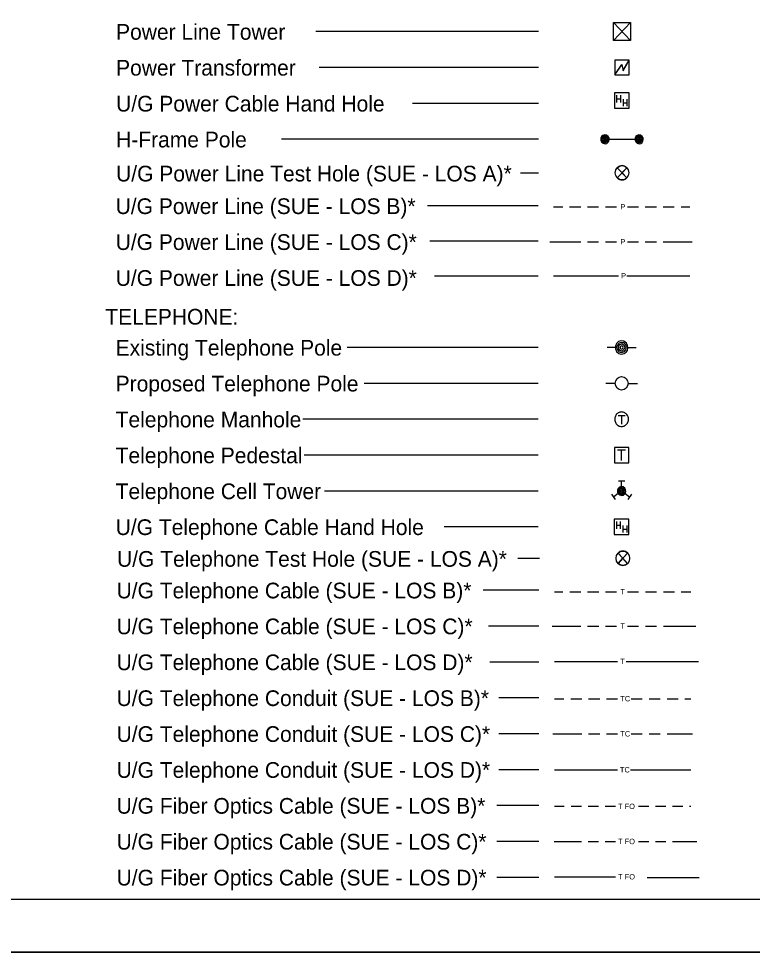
# Model space of a CAD drawing. Extents: x 2025847 to 2026166, y 840763 to 840870.
# Drawn here: x 2026094.71 to 2026130.13, y 840778.42 to 840823.5 of the extents above; entities that cross this region are included whole.
import ezdxf

# ---------------------------------------------------------------- set-up
doc = ezdxf.new("R2010")
doc.units = 0
for name, color, linetype in [('Exist Utilities Power Test Hole SUE LOS A CELL', 7, 'Continuous'), ('Exist Utilities Telephone Test Hole SUE LOS A CELL', 7, 'Continuous'), ('Sheet_Plan', 7, 'Continuous'), ('Sheet_Plot_Border_Outside_CELL', 7, 'Continuous'), ('Sheet_Symbology', 7, 'Continuous'), ('z - Construction', 7, 'Continuous')]:
    doc.layers.add(name, color=color, linetype=linetype)

msp = doc.modelspace()

# ---------------------------------------------------------------- linework, layer by layer
at = {"layer": 'Exist Utilities Power Test Hole SUE LOS A CELL'}
for points in [[(2026124.072, 840816.309), (2026123.607, 840815.819), (2026123.84, 840816.064), (2026123.607, 840816.309), (2026124.072, 840815.819)], [(2026123.607, 840816.309), (2026123.84, 840816.064), (2026124.072, 840816.309)], [(2026124.072, 840815.819), (2026123.84, 840816.064), (2026123.607, 840815.819)]]:
    msp.add_lwpolyline(points, dxfattribs=at)
for start_param, end_param in [(2.356194, 3.926991), (5.497787, 7.068583)]:
    msp.add_ellipse((2026123.84, 840816.064), major_axis=(0, -0.346), ratio=0.95, start_param=start_param, end_param=end_param, dxfattribs=at)
msp.add_ellipse((2026123.84, 840816.064), major_axis=(0, -0.346), ratio=0.95, dxfattribs=at)
at = {"layer": 'Exist Utilities Telephone Test Hole SUE LOS A CELL'}
for points in [[(2026124.111, 840797.692), (2026123.646, 840797.203), (2026123.879, 840797.448), (2026123.646, 840797.692), (2026124.111, 840797.203)], [(2026123.646, 840797.692), (2026123.879, 840797.448), (2026124.111, 840797.692)], [(2026124.111, 840797.203), (2026123.879, 840797.448), (2026123.646, 840797.203)]]:
    msp.add_lwpolyline(points, dxfattribs=at)
msp.add_ellipse((2026123.879, 840797.448), major_axis=(0, -0.346), ratio=0.95, dxfattribs=at)
for start_param, end_param in [(2.356194, 3.926991), (5.497787, 7.068583)]:
    msp.add_ellipse((2026123.879, 840797.448), major_axis=(0, -0.346), ratio=0.95, start_param=start_param, end_param=end_param, dxfattribs=at)
at = {"layer": 'Sheet_Plan'}
msp.add_line((2026024.668, 840780.981), (2026164.546, 840780.981), dxfattribs=at)
at = {"layer": 'Sheet_Plot_Border_Outside_CELL'}
msp.add_lwpolyline([(2026023.879, 840870.085), (2026165.546, 840870.085), (2026165.546, 840778.419), (2026023.879, 840778.419)], close=True, dxfattribs=at)
at = {"layer": 'Sheet_Symbology'}
for p, q in [((2026124.255, 840823.316), (2026123.433, 840822.45)), ((2026124.255, 840822.45), (2026123.433, 840823.316)), ((2026119.807, 840822.881), (2026109.051, 840822.881)), ((2026119.807, 840821.148), (2026109.218, 840821.148)), ((2026123.572, 840819.812), (2026123.572, 840819.463)), ((2026123.572, 840819.635), (2026123.762, 840819.635)), ((2026123.762, 840819.812), (2026123.762, 840819.463)), ((2026123.889, 840819.622), (2026123.889, 840819.273)), ((2026124.079, 840819.622), (2026124.079, 840819.273)), ((2026119.807, 840819.415), (2026113.725, 840819.415)), ((2026123.889, 840819.444), (2026124.079, 840819.444)), ((2026119.807, 840817.682), (2026107.403, 840817.682)), ((2026123.019, 840817.682), (2026124.665, 840817.682)), ((2026119.807, 840816.037), (2026118.932, 840816.037)), ((2026119.785, 840814.463), (2026114.441, 840814.463)), ((2026120.527, 840814.421), (2026120.979, 840814.421)), ((2026121.309, 840814.421), (2026121.844, 840814.421)), ((2026122.173, 840814.421), (2026122.708, 840814.421)), ((2026123.037, 840814.421), (2026123.572, 840814.421)), ((2026124.099, 840814.421), (2026124.634, 840814.421)), ((2026124.963, 840814.421), (2026125.498, 840814.421)), ((2026125.828, 840814.421), (2026126.363, 840814.421)), ((2026126.692, 840814.421), (2026127.112, 840814.421)), ((2026119.785, 840812.763), (2026114.567, 840812.763)), ((2026120.36, 840812.73), (2026121.844, 840812.73)), ((2026122.173, 840812.73), (2026122.708, 840812.73)), ((2026123.037, 840812.73), (2026123.572, 840812.73)), ((2026124.099, 840812.73), (2026124.634, 840812.73)), ((2026124.963, 840812.73), (2026125.498, 840812.73)), ((2026125.828, 840812.73), (2026127.229, 840812.73)), ((2026119.785, 840811.064), (2026114.789, 840811.064)), ((2026120.527, 840811.088), (2026123.662, 840811.088)), ((2026124.073, 840811.088), (2026127.112, 840811.088)), ((2026119.785, 840807.628), (2026110.574, 840807.628)), ((2026123.515, 840807.628), (2026123.12, 840807.628)), ((2026124.123, 840807.628), (2026124.518, 840807.628)), ((2026119.785, 840805.895), (2026111.383, 840805.895)), ((2026123.514, 840805.894), (2026123.051, 840805.894)), ((2026124.131, 840805.894), (2026124.594, 840805.894)), ((2026123.99, 840804.325), (2026123.651, 840804.325)), ((2026123.819, 840804.325), (2026123.819, 840803.931)), ((2026119.785, 840804.162), (2026108.436, 840804.162)), ((2026123.627, 840802.69), (2026124.012, 840802.69)), ((2026123.819, 840802.168), (2026123.819, 840802.69)), ((2026119.785, 840802.429), (2026108.494, 840802.429)), ((2026123.665, 840801.186), (2026123.974, 840801.186)), ((2026123.819, 840800.909), (2026123.819, 840801.186)), ((2026119.785, 840800.696), (2026109.477, 840800.696)), ((2026123.527, 840800.282), (2026123.35, 840800.548)), ((2026123.654, 840800.574), (2026123.438, 840800.415)), ((2026123.985, 840800.574), (2026124.201, 840800.415)), ((2026124.29, 840800.548), (2026124.112, 840800.282)), ((2026119.785, 840798.963), (2026115.254, 840798.963)), ((2026123.567, 840799.225), (2026123.567, 840798.876)), ((2026123.567, 840799.047), (2026123.756, 840799.047)), ((2026123.756, 840799.225), (2026123.756, 840798.876)), ((2026123.884, 840799.035), (2026123.884, 840798.686)), ((2026123.884, 840798.857), (2026124.073, 840798.857)), ((2026124.073, 840799.035), (2026124.073, 840798.686)), ((2026119.852, 840797.431), (2026118.81, 840797.431)), ((2026119.83, 840795.904), (2026117.131, 840795.904)), ((2026120.572, 840795.835), (2026120.985, 840795.835)), ((2026121.314, 840795.835), (2026121.849, 840795.835)), ((2026122.179, 840795.835), (2026122.714, 840795.835)), ((2026123.043, 840795.835), (2026123.578, 840795.835)), ((2026124.105, 840795.835), (2026124.64, 840795.835)), ((2026124.969, 840795.835), (2026125.504, 840795.835)), ((2026125.834, 840795.835), (2026126.369, 840795.835)), ((2026126.698, 840795.835), (2026127.157, 840795.835)), ((2026119.83, 840794.171), (2026117.391, 840794.171)), ((2026120.469, 840794.171), (2026121.849, 840794.171)), ((2026122.179, 840794.171), (2026122.714, 840794.171)), ((2026123.043, 840794.171), (2026123.578, 840794.171)), ((2026124.105, 840794.171), (2026124.64, 840794.171)), ((2026124.969, 840794.171), (2026125.504, 840794.171)), ((2026125.834, 840794.171), (2026127.401, 840794.171)), ((2026119.83, 840792.438), (2026117.454, 840792.438)), ((2026120.572, 840792.469), (2026123.628, 840792.469)), ((2026124.039, 840792.469), (2026127.528, 840792.469)), ((2026119.83, 840790.705), (2026117.898, 840790.705)), ((2026120.572, 840790.668), (2026121.031, 840790.668)), ((2026121.361, 840790.668), (2026121.896, 840790.668)), ((2026122.225, 840790.668), (2026122.76, 840790.668)), ((2026123.089, 840790.668), (2026123.624, 840790.668)), ((2026124.283, 840790.668), (2026124.818, 840790.668)), ((2026125.147, 840790.668), (2026125.682, 840790.668)), ((2026126.012, 840790.668), (2026126.547, 840790.668)), ((2026126.876, 840790.668), (2026127.157, 840790.668)), ((2026119.83, 840788.972), (2026117.898, 840788.972)), ((2026120.493, 840788.972), (2026121.896, 840788.972)), ((2026122.225, 840788.972), (2026122.76, 840788.972)), ((2026123.089, 840788.972), (2026123.624, 840788.972)), ((2026124.283, 840788.972), (2026124.818, 840788.972)), ((2026125.147, 840788.972), (2026125.682, 840788.972)), ((2026126.012, 840788.972), (2026127.236, 840788.972)), ((2026119.83, 840787.239), (2026117.898, 840787.239)), ((2026120.572, 840787.235), (2026123.624, 840787.235)), ((2026124.242, 840787.235), (2026127.157, 840787.235)), ((2026119.83, 840785.506), (2026117.803, 840785.506)), ((2026120.572, 840785.469), (2026121.052, 840785.469)), ((2026121.381, 840785.469), (2026121.875, 840785.469)), ((2026122.204, 840785.469), (2026122.698, 840785.469)), ((2026123.028, 840785.469), (2026123.522, 840785.469)), ((2026124.633, 840785.469), (2026125.127, 840785.469)), ((2026125.456, 840785.469), (2026125.95, 840785.469)), ((2026126.279, 840785.469), (2026126.773, 840785.469)), ((2026127.102, 840785.469), (2026127.157, 840785.469)), ((2026119.83, 840783.773), (2026117.803, 840783.773)), ((2026120.557, 840783.773), (2026121.875, 840783.773)), ((2026122.204, 840783.773), (2026122.698, 840783.773)), ((2026123.028, 840783.773), (2026123.522, 840783.773)), ((2026124.633, 840783.773), (2026125.127, 840783.773)), ((2026125.456, 840783.773), (2026125.95, 840783.773)), ((2026126.279, 840783.773), (2026127.457, 840783.773)), ((2026119.83, 840782.04), (2026117.803, 840782.04)), ((2026120.572, 840782.069), (2026123.525, 840782.069)), ((2026125.047, 840782.036), (2026127.568, 840782.036))]:
    msp.add_line(p, q, dxfattribs=at)
for points in [[(2026124.255, 840822.45), (2026123.433, 840822.45), (2026123.433, 840823.316), (2026124.255, 840823.316), (2026124.255, 840822.45), (2026123.433, 840822.45), (2026123.433, 840823.316), (2026124.255, 840823.316), (2026124.255, 840822.45)], [(2026123.499, 840820.787), (2026123.823, 840821.277), (2026123.902, 840821.01), (2026124.185, 840821.509)], [(2026123.499, 840820.787), (2026123.825, 840821.297), (2026123.899, 840820.99), (2026124.185, 840821.509)], [(2026123.499, 840820.787), (2026124.185, 840820.787), (2026124.185, 840821.509), (2026123.499, 840821.509), (2026123.499, 840820.787)], [(2026123.47, 840819.177), (2026124.179, 840819.177), (2026124.179, 840819.923), (2026123.47, 840819.923), (2026123.47, 840819.177)], [(2026123.169, 840817.682), (2026123.164, 840817.72), (2026123.152, 840817.754), (2026123.132, 840817.784), (2026123.108, 840817.81), (2026123.079, 840817.827), (2026123.043, 840817.835), (2026123.01, 840817.84), (2026122.974, 840817.831), (2026122.942, 840817.818), (2026122.917, 840817.797), (2026122.893, 840817.767), (2026122.877, 840817.737), (2026122.869, 840817.699), (2026122.869, 840817.665), (2026122.877, 840817.626), (2026122.893, 840817.596), (2026122.917, 840817.566), (2026122.942, 840817.545), (2026122.974, 840817.532), (2026123.01, 840817.524), (2026123.043, 840817.528), (2026123.079, 840817.537), (2026123.108, 840817.554), (2026123.132, 840817.579), (2026123.152, 840817.609), (2026123.164, 840817.643), (2026123.169, 840817.682)], [(2026123.12, 840817.682), (2026123.116, 840817.712), (2026123.104, 840817.741), (2026123.083, 840817.763), (2026123.059, 840817.78), (2026123.035, 840817.788), (2026123.002, 840817.788), (2026122.978, 840817.78), (2026122.954, 840817.763), (2026122.934, 840817.741), (2026122.921, 840817.712), (2026122.917, 840817.682), (2026122.921, 840817.652), (2026122.934, 840817.622), (2026122.954, 840817.601), (2026122.978, 840817.584), (2026123.002, 840817.575), (2026123.035, 840817.575), (2026123.059, 840817.584), (2026123.083, 840817.601), (2026123.104, 840817.622), (2026123.116, 840817.652), (2026123.12, 840817.682)], [(2026124.815, 840817.682), (2026124.811, 840817.72), (2026124.799, 840817.754), (2026124.778, 840817.784), (2026124.754, 840817.81), (2026124.726, 840817.827), (2026124.689, 840817.835), (2026124.657, 840817.84), (2026124.62, 840817.831), (2026124.588, 840817.818), (2026124.564, 840817.797), (2026124.539, 840817.767), (2026124.523, 840817.737), (2026124.515, 840817.699), (2026124.515, 840817.665), (2026124.523, 840817.626), (2026124.539, 840817.596), (2026124.564, 840817.566), (2026124.588, 840817.545), (2026124.62, 840817.532), (2026124.657, 840817.524), (2026124.689, 840817.528), (2026124.726, 840817.537), (2026124.754, 840817.554), (2026124.778, 840817.579), (2026124.799, 840817.609), (2026124.811, 840817.643), (2026124.815, 840817.682)], [(2026124.766, 840817.682), (2026124.762, 840817.712), (2026124.75, 840817.741), (2026124.73, 840817.763), (2026124.705, 840817.78), (2026124.681, 840817.788), (2026124.649, 840817.788), (2026124.624, 840817.78), (2026124.6, 840817.763), (2026124.58, 840817.741), (2026124.568, 840817.712), (2026124.564, 840817.682), (2026124.568, 840817.652), (2026124.58, 840817.622), (2026124.6, 840817.601), (2026124.624, 840817.584), (2026124.649, 840817.575), (2026124.681, 840817.575), (2026124.705, 840817.584), (2026124.73, 840817.601), (2026124.75, 840817.622), (2026124.762, 840817.652), (2026124.766, 840817.682)], [(2026123.067, 840817.682), (2026123.063, 840817.703), (2026123.051, 840817.72), (2026123.035, 840817.729), (2026123.015, 840817.733), (2026122.994, 840817.724), (2026122.978, 840817.712), (2026122.97, 840817.69), (2026122.97, 840817.673), (2026122.978, 840817.652), (2026122.994, 840817.639), (2026123.015, 840817.63), (2026123.035, 840817.635), (2026123.051, 840817.643), (2026123.063, 840817.66), (2026123.067, 840817.682)], [(2026124.713, 840817.682), (2026124.709, 840817.703), (2026124.697, 840817.72), (2026124.681, 840817.729), (2026124.661, 840817.733), (2026124.641, 840817.724), (2026124.624, 840817.712), (2026124.616, 840817.69), (2026124.616, 840817.673), (2026124.624, 840817.652), (2026124.641, 840817.639), (2026124.661, 840817.63), (2026124.681, 840817.635), (2026124.697, 840817.643), (2026124.709, 840817.66), (2026124.713, 840817.682)], [(2026124.044, 840807.628), (2026124.038, 840807.685), (2026124.02, 840807.736), (2026123.989, 840807.781), (2026123.953, 840807.82), (2026123.91, 840807.845), (2026123.856, 840807.858), (2026123.807, 840807.865), (2026123.752, 840807.852), (2026123.704, 840807.832), (2026123.667, 840807.801), (2026123.631, 840807.756), (2026123.607, 840807.711), (2026123.594, 840807.653), (2026123.594, 840807.602), (2026123.607, 840807.545), (2026123.631, 840807.5), (2026123.667, 840807.455), (2026123.704, 840807.423), (2026123.752, 840807.404), (2026123.807, 840807.391), (2026123.856, 840807.398), (2026123.91, 840807.41), (2026123.953, 840807.436), (2026123.989, 840807.474), (2026124.02, 840807.519), (2026124.038, 840807.57), (2026124.044, 840807.628)], [(2026123.971, 840807.628), (2026123.965, 840807.673), (2026123.947, 840807.717), (2026123.916, 840807.749), (2026123.88, 840807.775), (2026123.844, 840807.788), (2026123.795, 840807.788), (2026123.758, 840807.775), (2026123.722, 840807.749), (2026123.692, 840807.717), (2026123.673, 840807.673), (2026123.667, 840807.628), (2026123.673, 840807.583), (2026123.692, 840807.538), (2026123.722, 840807.506), (2026123.758, 840807.481), (2026123.795, 840807.468), (2026123.844, 840807.468), (2026123.88, 840807.481), (2026123.916, 840807.506), (2026123.947, 840807.538), (2026123.965, 840807.583), (2026123.971, 840807.628)], [(2026123.892, 840807.628), (2026123.886, 840807.66), (2026123.868, 840807.685), (2026123.844, 840807.698), (2026123.813, 840807.705), (2026123.783, 840807.692), (2026123.758, 840807.673), (2026123.746, 840807.641), (2026123.746, 840807.615), (2026123.758, 840807.583), (2026123.783, 840807.564), (2026123.813, 840807.551), (2026123.844, 840807.557), (2026123.868, 840807.57), (2026123.886, 840807.596), (2026123.892, 840807.628)], [(2026123.819, 840804.514), (2026123.776, 840804.511), (2026123.736, 840804.502), (2026123.696, 840804.488), (2026123.659, 840804.469), (2026123.624, 840804.446), (2026123.592, 840804.418), (2026123.562, 840804.384), (2026123.538, 840804.35), (2026123.517, 840804.311), (2026123.504, 840804.269), (2026123.493, 840804.227), (2026123.488, 840804.184), (2026123.488, 840804.139), (2026123.493, 840804.097), (2026123.504, 840804.052), (2026123.517, 840804.013), (2026123.538, 840803.973), (2026123.562, 840803.939), (2026123.592, 840803.906), (2026123.624, 840803.878), (2026123.659, 840803.855), (2026123.696, 840803.835), (2026123.736, 840803.821), (2026123.779, 840803.813), (2026123.819, 840803.81), (2026123.862, 840803.813), (2026123.902, 840803.821), (2026123.942, 840803.835), (2026123.98, 840803.855), (2026124.014, 840803.878), (2026124.046, 840803.906), (2026124.076, 840803.939), (2026124.1, 840803.973), (2026124.121, 840804.013), (2026124.135, 840804.055), (2026124.145, 840804.097), (2026124.151, 840804.139), (2026124.151, 840804.184), (2026124.145, 840804.227), (2026124.135, 840804.272), (2026124.121, 840804.311), (2026124.1, 840804.35), (2026124.076, 840804.384), (2026124.046, 840804.418), (2026124.014, 840804.446), (2026123.98, 840804.469), (2026123.942, 840804.488), (2026123.902, 840804.502), (2026123.859, 840804.511), (2026123.819, 840804.514)], [(2026123.473, 840802.064), (2026124.166, 840802.064), (2026124.166, 840802.794), (2026123.473, 840802.794), (2026123.473, 840802.064)], [(2026123.969, 840800.696), (2026123.965, 840800.734), (2026123.953, 840800.768), (2026123.933, 840800.798), (2026123.908, 840800.824), (2026123.88, 840800.841), (2026123.843, 840800.849), (2026123.811, 840800.854), (2026123.775, 840800.845), (2026123.742, 840800.832), (2026123.718, 840800.811), (2026123.694, 840800.781), (2026123.677, 840800.751), (2026123.669, 840800.713), (2026123.669, 840800.679), (2026123.677, 840800.64), (2026123.694, 840800.611), (2026123.718, 840800.581), (2026123.742, 840800.559), (2026123.775, 840800.547), (2026123.811, 840800.538), (2026123.843, 840800.542), (2026123.88, 840800.551), (2026123.908, 840800.568), (2026123.933, 840800.594), (2026123.953, 840800.623), (2026123.965, 840800.658), (2026123.969, 840800.696)], [(2026123.92, 840800.696), (2026123.916, 840800.726), (2026123.904, 840800.755), (2026123.884, 840800.777), (2026123.86, 840800.794), (2026123.835, 840800.802), (2026123.803, 840800.802), (2026123.779, 840800.794), (2026123.754, 840800.777), (2026123.734, 840800.755), (2026123.722, 840800.726), (2026123.718, 840800.696), (2026123.722, 840800.666), (2026123.734, 840800.636), (2026123.754, 840800.615), (2026123.779, 840800.598), (2026123.803, 840800.589), (2026123.835, 840800.589), (2026123.86, 840800.598), (2026123.884, 840800.615), (2026123.904, 840800.636), (2026123.916, 840800.666), (2026123.92, 840800.696)], [(2026123.868, 840800.696), (2026123.864, 840800.717), (2026123.852, 840800.734), (2026123.835, 840800.743), (2026123.815, 840800.747), (2026123.795, 840800.739), (2026123.779, 840800.726), (2026123.771, 840800.704), (2026123.771, 840800.687), (2026123.779, 840800.666), (2026123.795, 840800.653), (2026123.815, 840800.645), (2026123.835, 840800.649), (2026123.852, 840800.658), (2026123.864, 840800.675), (2026123.868, 840800.696)], [(2026123.465, 840798.59), (2026124.174, 840798.59), (2026124.174, 840799.336), (2026123.465, 840799.336), (2026123.465, 840798.59)]]:
    msp.add_lwpolyline(points, dxfattribs=at)
for points in [[(2026123.019, 840817.468), (2026123.104, 840817.485), (2026123.16, 840817.528), (2026123.205, 840817.588), (2026123.221, 840817.669), (2026123.213, 840817.746), (2026123.173, 840817.822), (2026123.092, 840817.886), (2026122.998, 840817.895), (2026122.917, 840817.869), (2026122.852, 840817.81), (2026122.82, 840817.729), (2026122.82, 840817.635), (2026122.852, 840817.554), (2026122.925, 840817.49)], [(2026124.665, 840817.468), (2026124.75, 840817.485), (2026124.807, 840817.528), (2026124.851, 840817.588), (2026124.867, 840817.669), (2026124.859, 840817.746), (2026124.819, 840817.822), (2026124.738, 840817.886), (2026124.645, 840817.895), (2026124.564, 840817.869), (2026124.499, 840817.81), (2026124.466, 840817.729), (2026124.466, 840817.635), (2026124.499, 840817.554), (2026124.572, 840817.49)], [(2026123.819, 840807.308), (2026123.947, 840807.333), (2026124.032, 840807.398), (2026124.099, 840807.487), (2026124.123, 840807.609), (2026124.111, 840807.724), (2026124.05, 840807.839), (2026123.929, 840807.935), (2026123.789, 840807.948), (2026123.667, 840807.909), (2026123.57, 840807.82), (2026123.522, 840807.698), (2026123.522, 840807.557), (2026123.57, 840807.436), (2026123.679, 840807.34)], [(2026123.819, 840800.483), (2026123.904, 840800.5), (2026123.961, 840800.542), (2026124.006, 840800.602), (2026124.022, 840800.683), (2026124.014, 840800.76), (2026123.973, 840800.837), (2026123.892, 840800.901), (2026123.799, 840800.909), (2026123.718, 840800.883), (2026123.653, 840800.824), (2026123.621, 840800.743), (2026123.621, 840800.649), (2026123.653, 840800.568), (2026123.726, 840800.504)]]:
    msp.add_lwpolyline(points, close=True, dxfattribs=at)
msp.add_ellipse((2026123.819, 840805.895), major_axis=(0, 0.325), ratio=0.95, dxfattribs=at)
at = {"layer": 'z - Construction'}
msp.add_line((2026023.879, 840778.419), (2026165.546, 840778.419), dxfattribs=at)

# ---------------------------------------------------------------- texts
at = {"layer": 'Sheet_Symbology'}
for s, height, p in [('Power Line Tower', 0.75818, (2026099.415, 840822.489)), ('Power Transformer', 0.75818, (2026099.414, 840820.756)), ('U/G Power Cable Hand Hole', 0.75818, (2026099.416, 840819.021)), ('H-Frame Pole', 0.75818, (2026099.416, 840817.288)), ('U/G Power Line Test Hole (SUE - LOS A)*', 0.75818, (2026099.416, 840815.644)), ('U/G Power Line (SUE - LOS B)*', 0.75818, (2026099.394, 840814.07)), ('P', 0.26, (2026123.762, 840814.291)), ('U/G Power Line (SUE - LOS C)*', 0.75818, (2026099.396, 840812.336)), ('P', 0.26, (2026123.762, 840812.6)), ('U/G Power Line (SUE - LOS D)*', 0.75818, (2026099.398, 840810.602)), ('P', 0.26, (2026123.794, 840810.958)), ('TELEPHONE:', 0.7582, (2026098.895, 840808.733)), ('Existing Telephone Pole', 0.75818, (2026099.394, 840807.235)), ('Proposed Telephone Pole', 0.75818, (2026099.394, 840805.502)), ('Telephone Manhole', 0.75818, (2026099.394, 840803.769)), ('Telephone Pedestal', 0.75818, (2026099.394, 840802.036)), ('Telephone Cell Tower', 0.75818, (2026099.395, 840800.303)), ('U/G Telephone Cable Hand Hole', 0.75818, (2026099.395, 840798.57)), ('U/G Telephone Test Hole (SUE - LOS A)*', 0.75818, (2026099.462, 840797.038)), ('U/G Telephone Cable (SUE - LOS B)*', 0.75818, (2026099.44, 840795.511)), ('T', 0.26, (2026123.763, 840795.705)), ('U/G Telephone Cable (SUE - LOS C)*', 0.75818, (2026099.44, 840793.778)), ('T', 0.26, (2026123.763, 840794.041)), ('U/G Telephone Cable (SUE - LOS D)*', 0.75818, (2026099.44, 840792.045)), ('T', 0.26, (2026123.755, 840792.339)), ('U/G Telephone Conduit (SUE - LOS B)*', 0.75818, (2026099.44, 840790.312)), ('TC', 0.2599, (2026123.756, 840790.538)), ('U/G Telephone Conduit (SUE - LOS C)*', 0.75818, (2026099.44, 840788.579)), ('TC', 0.2599, (2026123.756, 840788.842)), ('U/G Telephone Conduit (SUE - LOS D)*', 0.75818, (2026099.44, 840786.846)), ('TC', 0.2599, (2026123.736, 840787.105)), ('U/G Fiber Optics Cable (SUE - LOS B)*', 0.75818, (2026099.44, 840785.113)), ('T FO', 0.2599, (2026123.645, 840785.339)), ('U/G Fiber Optics Cable (SUE - LOS C)*', 0.75818, (2026099.44, 840783.38)), ('T FO', 0.2599, (2026123.645, 840783.643)), ('U/G Fiber Optics Cable (SUE - LOS D)*', 0.75818, (2026099.44, 840781.647)), ('T FO', 0.2599, (2026123.648, 840781.939))]:
    msp.add_text(s, height=height, dxfattribs=at).set_placement(p)

doc.saveas('drawing.dxf')
